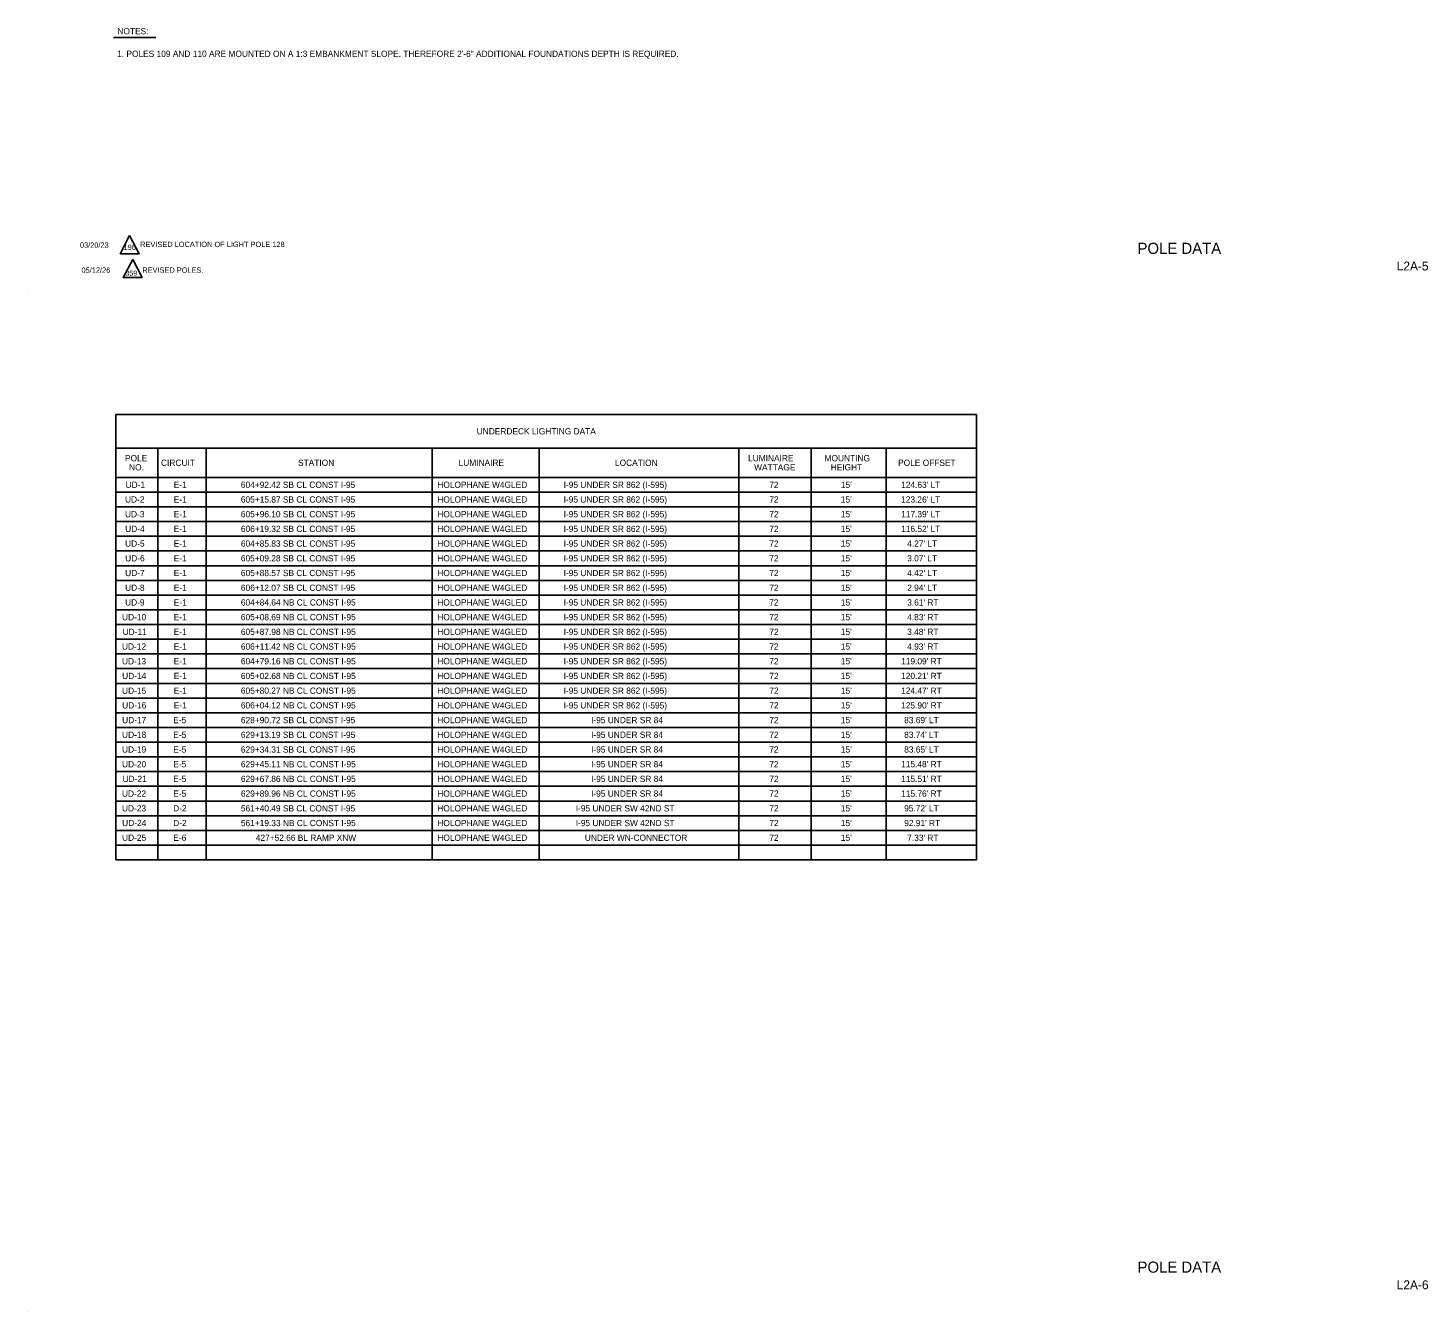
# Model space of a CAD drawing. Extents: x -818.1 to -802.4, y -2221.2 to -2187.7.
# Drawn here: x -818.09 to -802.38, y -2221.15 to -2206.75 of the extents above; entities that cross this region are included whole.
import ezdxf

# ---------------------------------------------------------------- set-up
doc = ezdxf.new("R2010")
doc.units = 0
for name, color, linetype in [('PlotBorder_dp', 7, 'Continuous'), ('SheetBorder_dp', 7, 'Continuous'), ('SheetLines_dp', 7, 'Continuous'), ('TextMinor', 7, 'Continuous'), ('TextMisc', 7, 'Continuous'), ('TextNotes', 7, 'Continuous'), ('TextShtNo', 7, 'Continuous'), ('TextTitle', 7, 'Continuous')]:
    doc.layers.add(name, color=color, linetype=linetype)

msp = doc.modelspace()

# ---------------------------------------------------------------- linework, layer by layer
at = {"layer": 'PlotBorder_dp'}
for p, q in [((-816.628, -2211.46), (-816.628, -2216.08)), ((-816.628, -2211.46), (-816.628, -2216.08)), ((-816.088, -2211.46), (-816.088, -2216.08)), ((-816.088, -2211.46), (-816.088, -2216.08)), ((-813.553, -2211.46), (-813.553, -2212.615)), ((-813.553, -2211.46), (-813.553, -2216.08)), ((-812.353, -2211.46), (-812.353, -2216.08)), ((-812.353, -2211.46), (-812.353, -2216.08)), ((-810.111, -2211.46), (-810.111, -2216.08)), ((-810.111, -2211.46), (-810.111, -2216.08)), ((-809.301, -2211.46), (-809.301, -2216.08)), ((-809.301, -2211.46), (-809.301, -2216.08)), ((-808.461, -2211.46), (-808.461, -2212.285)), ((-808.461, -2211.46), (-808.461, -2216.08)), ((-817.101, -2211.79), (-807.448, -2211.79)), ((-808.461, -2211.79), (-807.448, -2211.79)), ((-808.461, -2212.45), (-808.461, -2213.275)), ((-813.553, -2212.78), (-813.553, -2216.08)), ((-808.461, -2213.44), (-808.461, -2216.08))]:
    msp.add_line(p, q, dxfattribs=at)
at = {"layer": 'SheetBorder_dp'}
msp.add_line((-817.128, -2206.854), (-816.652, -2206.854), dxfattribs=at)
at = {"layer": 'SheetLines_dp'}
for p, q in [((-817.101, -2211.085), (-807.448, -2211.085)), ((-817.101, -2211.085), (-817.101, -2216.08)), ((-807.448, -2216.08), (-807.448, -2211.085)), ((-817.101, -2211.46), (-807.448, -2211.46)), ((-817.101, -2211.46), (-807.448, -2211.46)), ((-807.448, -2211.79), (-807.448, -2211.955)), ((-807.448, -2212.285), (-807.448, -2212.615)), ((-807.448, -2213.11), (-807.448, -2213.605)), ((-807.448, -2214.43), (-807.448, -2214.595)), ((-807.448, -2215.255), (-807.448, -2215.42)), ((-807.448, -2215.915), (-807.448, -2216.08)), ((-817.101, -2216.08), (-809.301, -2216.08)), ((-809.301, -2216.08), (-808.461, -2216.08)), ((-808.461, -2216.08), (-807.448, -2216.08))]:
    msp.add_line(p, q, dxfattribs=at)
at = {"layer": 'TextMinor'}
for p, q in [((-817.101, -2211.79), (-808.461, -2211.79)), ((-817.101, -2211.955), (-807.448, -2211.955)), ((-817.101, -2211.955), (-807.448, -2211.955)), ((-817.101, -2212.12), (-807.448, -2212.12)), ((-817.101, -2212.12), (-807.448, -2212.12)), ((-817.101, -2212.285), (-807.448, -2212.285)), ((-817.101, -2212.285), (-807.448, -2212.285)), ((-817.101, -2212.45), (-807.448, -2212.45)), ((-817.101, -2212.45), (-807.448, -2212.45)), ((-817.101, -2212.615), (-807.448, -2212.615)), ((-817.101, -2212.615), (-807.448, -2212.615)), ((-817.101, -2212.78), (-816.088, -2212.78)), ((-817.101, -2212.78), (-807.448, -2212.78)), ((-813.553, -2212.78), (-807.448, -2212.78)), ((-817.101, -2212.945), (-807.448, -2212.945)), ((-817.101, -2212.945), (-807.448, -2212.945)), ((-817.101, -2213.11), (-807.448, -2213.11)), ((-817.101, -2213.11), (-807.448, -2213.11)), ((-817.101, -2213.275), (-807.448, -2213.275)), ((-817.101, -2213.275), (-807.448, -2213.275)), ((-817.101, -2213.44), (-807.448, -2213.44)), ((-817.101, -2213.44), (-807.448, -2213.44)), ((-817.101, -2213.605), (-807.448, -2213.605)), ((-817.101, -2213.605), (-807.448, -2213.605)), ((-817.101, -2213.77), (-807.448, -2213.77)), ((-817.101, -2213.77), (-807.448, -2213.77)), ((-817.101, -2213.935), (-807.448, -2213.935)), ((-817.101, -2213.935), (-807.448, -2213.935)), ((-817.101, -2214.1), (-807.448, -2214.1)), ((-817.101, -2214.1), (-807.448, -2214.1)), ((-817.101, -2214.265), (-807.448, -2214.265)), ((-817.101, -2214.265), (-807.448, -2214.265)), ((-817.101, -2214.43), (-807.448, -2214.43)), ((-817.101, -2214.43), (-807.448, -2214.43)), ((-817.101, -2214.595), (-807.448, -2214.595)), ((-817.101, -2214.595), (-807.448, -2214.595)), ((-817.101, -2214.76), (-807.448, -2214.76)), ((-817.101, -2214.76), (-807.448, -2214.76)), ((-817.101, -2214.925), (-807.448, -2214.925)), ((-817.101, -2214.925), (-807.448, -2214.925)), ((-817.101, -2215.09), (-807.448, -2215.09)), ((-817.101, -2215.09), (-807.448, -2215.09)), ((-817.101, -2215.255), (-807.448, -2215.255)), ((-817.101, -2215.255), (-807.448, -2215.255)), ((-817.101, -2215.42), (-807.448, -2215.42)), ((-817.101, -2215.42), (-807.448, -2215.42)), ((-817.101, -2215.585), (-816.628, -2215.585)), ((-817.101, -2215.585), (-807.448, -2215.585)), ((-813.553, -2215.585), (-812.353, -2215.585)), ((-817.101, -2215.75), (-816.628, -2215.75)), ((-817.101, -2215.75), (-807.448, -2215.75)), ((-813.553, -2215.75), (-812.353, -2215.75)), ((-817.101, -2215.915), (-807.448, -2215.915)), ((-813.553, -2215.915), (-812.353, -2215.915))]:
    msp.add_line(p, q, dxfattribs=at)
at = {"layer": 'TextShtNo'}
for p, q in [((-818.086, -2209.723), (-818.086, -2209.723)), ((-818.086, -2221.153), (-818.086, -2221.153))]:
    msp.add_line(p, q, dxfattribs=at)
at = {"layer": 'TextTitle'}
for points in [[(-816.946, -2209.076), (-817.052, -2209.281), (-816.839, -2209.281)], [(-816.911, -2209.344), (-817.017, -2209.547), (-816.806, -2209.547)]]:
    msp.add_lwpolyline(points, close=True, dxfattribs=at)

# ---------------------------------------------------------------- texts
at = {"layer": 'SheetBorder_dp'}
for s, p in [('NOTES:', (-817.083, -2206.818)), ('1. POLES 109 AND 110 ARE MOUNTED ON A 1:3 EMBANKMENT SLOPE. THEREFORE 2\'-6" ADDITIONAL FOUNDATIONS DEPTH IS REQUIRED.', (-817.086, -2207.072)), ('UNDERDECK LIGHTING DATA', (-813.053, -2211.307)), ('POLE', (-816.998, -2211.609)), ('CIRCUIT', (-816.594, -2211.66)), ('STATION', (-815.057, -2211.66)), ('LUMINAIRE', (-813.256, -2211.66)), ('LOCATION', (-811.502, -2211.66)), ('LUMINAIRE', (-810.009, -2211.609)), ('MOUNTING', (-809.151, -2211.609)), ('POLE OFFSET', (-808.326, -2211.66)), ('NO.', (-816.952, -2211.711)), ('WATTAGE', (-809.941, -2211.711)), ('HEIGHT', (-809.082, -2211.711)), ('UD-1', (-816.991, -2211.907)), ('E-1', (-816.451, -2211.907)), ('604+92.42 SB CL CONST I-95', (-815.698, -2211.907)), ('HOLOPHANE W4GLED', (-813.495, -2211.907)), (' I-95 UNDER SR 862 (I-595)', (-812.104, -2211.907)), ('72', (-809.771, -2211.907)), ("15'", (-808.969, -2211.907)), ("124.63' LT", (-808.292, -2211.907)), ('UD-2', (-816.998, -2212.072)), ('E-1', (-816.451, -2212.072)), ('605+15.87 SB CL CONST I-95', (-815.698, -2212.072)), ('HOLOPHANE W4GLED', (-813.495, -2212.072)), (' I-95 UNDER SR 862 (I-595)', (-812.104, -2212.072)), ('72', (-809.771, -2212.072)), ("15'", (-808.969, -2212.072)), ("123.26' LT", (-808.292, -2212.072)), ('UD-3', (-816.998, -2212.237)), ('E-1', (-816.451, -2212.237)), ('605+96.10 SB CL CONST I-95', (-815.698, -2212.237)), ('HOLOPHANE W4GLED', (-813.495, -2212.237)), (' I-95 UNDER SR 862 (I-595)', (-812.104, -2212.237)), ('72', (-809.771, -2212.237)), ("15'", (-808.969, -2212.237)), ("117.39' LT", (-808.292, -2212.237)), ('UD-4', (-816.996, -2212.402)), ('E-1', (-816.451, -2212.402)), ('606+19.32 SB CL CONST I-95', (-815.698, -2212.402)), ('HOLOPHANE W4GLED', (-813.495, -2212.402)), (' I-95 UNDER SR 862 (I-595)', (-812.104, -2212.402)), ('72', (-809.771, -2212.402)), ("15'", (-808.969, -2212.402)), ("116.52' LT", (-808.292, -2212.402)), ('UD-5', (-816.997, -2212.567)), ('E-1', (-816.451, -2212.567)), ('604+85.83 SB CL CONST I-95', (-815.698, -2212.567)), ('HOLOPHANE W4GLED', (-813.495, -2212.567)), (' I-95 UNDER SR 862 (I-595)', (-812.104, -2212.567)), ('72', (-809.771, -2212.567)), ("15'", (-808.969, -2212.567)), ("4.27' LT", (-808.224, -2212.567)), ('UD-6', (-816.996, -2212.732)), ('E-1', (-816.451, -2212.732)), ('605+09.28 SB CL CONST I-95', (-815.698, -2212.732)), ('HOLOPHANE W4GLED', (-813.495, -2212.732)), (' I-95 UNDER SR 862 (I-595)', (-812.104, -2212.732)), ('72', (-809.771, -2212.732)), ("15'", (-808.969, -2212.732)), ("3.07' LT", (-808.224, -2212.732)), ('UD-7', (-816.996, -2212.897)), ('E-1', (-816.451, -2212.897)), ('605+88.57 SB CL CONST I-95', (-815.698, -2212.897)), ('HOLOPHANE W4GLED', (-813.495, -2212.897)), (' I-95 UNDER SR 862 (I-595)', (-812.104, -2212.897)), ('72', (-809.771, -2212.897)), ("15'", (-808.969, -2212.897)), ("4.42' LT", (-808.224, -2212.897)), ('UD-8', (-816.997, -2213.062)), ('E-1', (-816.451, -2213.062)), ('606+12.07 SB CL CONST I-95', (-815.698, -2213.062)), ('HOLOPHANE W4GLED', (-813.495, -2213.062)), (' I-95 UNDER SR 862 (I-595)', (-812.104, -2213.062)), ('72', (-809.771, -2213.062)), ("15'", (-808.969, -2213.062)), ("2.94' LT", (-808.224, -2213.062)), ('UD-9', (-816.997, -2213.227)), ('E-1', (-816.451, -2213.227)), ('604+84.64 NB CL CONST I-95', (-815.698, -2213.227)), ('HOLOPHANE W4GLED', (-813.495, -2213.227)), (' I-95 UNDER SR 862 (I-595)', (-812.104, -2213.227)), ('72', (-809.771, -2213.227)), ("15'", (-808.969, -2213.227)), ("3.61' RT", (-808.224, -2213.227)), ('UD-10', (-817.031, -2213.392)), ('E-1', (-816.451, -2213.392)), ('605+08.69 NB CL CONST I-95', (-815.698, -2213.392)), ('HOLOPHANE W4GLED', (-813.495, -2213.392)), (' I-95 UNDER SR 862 (I-595)', (-812.104, -2213.392)), ('72', (-809.771, -2213.392)), ("15'", (-808.969, -2213.392)), ("4.83' RT", (-808.224, -2213.392)), ('UD-11', (-817.025, -2213.557)), ('E-1', (-816.451, -2213.557)), ('605+87.98 NB CL CONST I-95', (-815.698, -2213.557)), ('HOLOPHANE W4GLED', (-813.495, -2213.557)), (' I-95 UNDER SR 862 (I-595)', (-812.104, -2213.557)), ('72', (-809.771, -2213.557)), ("15'", (-808.969, -2213.557)), ("3.48' RT", (-808.224, -2213.557)), ('UD-12', (-817.032, -2213.722)), ('E-1', (-816.451, -2213.722)), ('606+11.42 NB CL CONST I-95', (-815.698, -2213.722)), ('HOLOPHANE W4GLED', (-813.495, -2213.722)), (' I-95 UNDER SR 862 (I-595)', (-812.104, -2213.722)), ('72', (-809.771, -2213.722)), ("15'", (-808.969, -2213.722)), ("4.93' RT", (-808.224, -2213.722)), ('UD-13', (-817.032, -2213.887)), ('E-1', (-816.451, -2213.887)), ('604+79.16 NB CL CONST I-95', (-815.698, -2213.887)), ('HOLOPHANE W4GLED', (-813.495, -2213.887)), (' I-95 UNDER SR 862 (I-595)', (-812.104, -2213.887)), ('72', (-809.771, -2213.887)), ("15'", (-808.969, -2213.887)), ("119.09' RT", (-808.292, -2213.887)), ('UD-14', (-817.03, -2214.052)), ('E-1', (-816.451, -2214.052)), ('605+02.68 NB CL CONST I-95', (-815.698, -2214.052)), ('HOLOPHANE W4GLED', (-813.495, -2214.052)), (' I-95 UNDER SR 862 (I-595)', (-812.104, -2214.052)), ('72', (-809.771, -2214.052)), ("15'", (-808.969, -2214.052)), ("120.21' RT", (-808.292, -2214.052)), ('UD-15', (-817.031, -2214.217)), ('E-1', (-816.451, -2214.217)), ('605+80.27 NB CL CONST I-95', (-815.698, -2214.217)), ('HOLOPHANE W4GLED', (-813.495, -2214.217)), (' I-95 UNDER SR 862 (I-595)', (-812.104, -2214.217)), ('72', (-809.771, -2214.217)), ("15'", (-808.969, -2214.217)), ("124.47' RT", (-808.292, -2214.217)), ('UD-16', (-817.03, -2214.382)), ('E-1', (-816.451, -2214.382)), ('606+04.12 NB CL CONST I-95', (-815.698, -2214.382)), ('HOLOPHANE W4GLED', (-813.495, -2214.382)), (' I-95 UNDER SR 862 (I-595)', (-812.104, -2214.382)), ('72', (-809.771, -2214.382)), ("15'", (-808.969, -2214.382)), ("125.90' RT", (-808.292, -2214.382)), ('UD-17', (-817.03, -2214.547)), ('E-5', (-816.457, -2214.547)), ('628+90.72 SB CL CONST I-95', (-815.698, -2214.547)), ('HOLOPHANE W4GLED', (-813.495, -2214.547)), ('I-95 UNDER SR 84', (-811.77, -2214.547)), ('72', (-809.771, -2214.547)), ("15'", (-808.969, -2214.547)), ("83.69' LT", (-808.258, -2214.547)), ('UD-18', (-817.031, -2214.712)), ('E-5', (-816.457, -2214.712)), ('629+13.19 SB CL CONST I-95', (-815.698, -2214.712)), ('HOLOPHANE W4GLED', (-813.495, -2214.712)), ('I-95 UNDER SR 84', (-811.77, -2214.712)), ('72', (-809.771, -2214.712)), ("15'", (-808.969, -2214.712)), ("83.74' LT", (-808.258, -2214.712)), ('UD-19', (-817.031, -2214.877)), ('E-5', (-816.457, -2214.877)), ('629+34.31 SB CL CONST I-95', (-815.698, -2214.877)), ('HOLOPHANE W4GLED', (-813.495, -2214.877)), ('I-95 UNDER SR 84', (-811.77, -2214.877)), ('72', (-809.771, -2214.877)), ("15'", (-808.969, -2214.877)), ("83.65' LT", (-808.258, -2214.877)), ('UD-20', (-817.031, -2215.042)), ('E-5', (-816.457, -2215.042)), ('629+45.11 NB CL CONST I-95', (-815.698, -2215.042)), ('HOLOPHANE W4GLED', (-813.495, -2215.042)), ('I-95 UNDER SR 84', (-811.77, -2215.042)), ('72', (-809.771, -2215.042)), ("15'", (-808.969, -2215.042)), ("115.48' RT", (-808.292, -2215.042)), ('UD-21', (-817.025, -2215.207)), ('E-5', (-816.457, -2215.207)), ('629+67.86 NB CL CONST I-95', (-815.698, -2215.207)), ('HOLOPHANE W4GLED', (-813.495, -2215.207)), ('I-95 UNDER SR 84', (-811.77, -2215.207)), ('72', (-809.771, -2215.207)), ("15'", (-808.969, -2215.207)), ("115.51' RT", (-808.292, -2215.207)), ('UD-22', (-817.032, -2215.372)), ('E-5', (-816.457, -2215.372)), ('629+89.96 NB CL CONST I-95', (-815.698, -2215.372)), ('HOLOPHANE W4GLED', (-813.495, -2215.372)), ('I-95 UNDER SR 84', (-811.77, -2215.372)), ('72', (-809.771, -2215.372)), ("15'", (-808.969, -2215.372)), ("115.76' RT", (-808.292, -2215.372)), ('UD-23', (-817.032, -2215.537)), ('D-2', (-816.458, -2215.537)), ('561+40.49 SB CL CONST I-95', (-815.698, -2215.537)), ('HOLOPHANE W4GLED', (-813.495, -2215.537)), ('I-95 UNDER SW 42ND ST', (-811.942, -2215.537)), ('72', (-809.771, -2215.537)), ("15'", (-808.969, -2215.537)), ("95.72' LT", (-808.258, -2215.537)), ('UD-24', (-817.03, -2215.702)), ('D-2', (-816.458, -2215.702)), ('561+19.33 NB CL CONST I-95', (-815.698, -2215.702)), ('HOLOPHANE W4GLED', (-813.495, -2215.702)), ('I-95 UNDER SW 42ND ST', (-811.942, -2215.702)), ('72', (-809.771, -2215.702)), ("15'", (-808.969, -2215.702)), ("92.91' RT", (-808.258, -2215.702)), ('UD-25', (-817.031, -2215.867)), ('E-6', (-816.456, -2215.867)), ('427+52.66 BL RAMP XNW', (-815.531, -2215.867)), ('HOLOPHANE W4GLED', (-813.495, -2215.867)), ('UNDER WN-CONNECTOR', (-811.84, -2215.867)), ('72', (-809.771, -2215.867)), ("15'", (-808.969, -2215.867)), ("7.33' RT", (-808.224, -2215.867))]:
    msp.add_text(s, height=0.07, dxfattribs=at).set_placement(p)
at = {"layer": 'TextMisc'}
for s, p in [('L2A-5 ', (-802.733, -2209.468)), ('L2A-6 ', (-802.733, -2220.898))]:
    msp.add_text(s, height=0.1, dxfattribs=at).set_placement(p)
at = {"layer": 'TextNotes'}
for p in [(-806.105, -2209.282), (-806.105, -2220.712)]:
    msp.add_text('          POLE DATA            ', height=0.125, dxfattribs=at).set_placement(p)
at = {"layer": 'TextTitle'}
for s, height, p in [('03/20/23', 0.06, (-817.504, -2209.213)), ('196', 0.06, (-817.014, -2209.238)), ('REVISED LOCATION OF LIGHT POLE 128', 0.06, (-816.828, -2209.205)), ('05/12/26', 0.06, (-817.486, -2209.494)), ('359', 0.057, (-816.993, -2209.527)), ('REVISED POLES.', 0.06, (-816.804, -2209.494))]:
    msp.add_text(s, height=height, dxfattribs=at).set_placement(p)

doc.saveas('drawing.dxf')
